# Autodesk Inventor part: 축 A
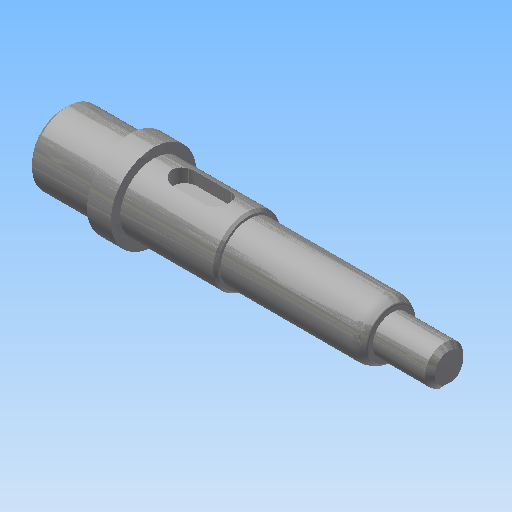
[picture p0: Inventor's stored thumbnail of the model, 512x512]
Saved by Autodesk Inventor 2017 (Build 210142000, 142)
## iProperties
Created: 2020-04
Part Number: 축 A
Material: 강철, 연강
Document SubType Name: Modeling
Designer: mduedu
Density: 7.86 g/cm^3
Mass: 83.1664 g
Surface Area: 37.6212 cm^2
Volume: 10.581 cm^3
Appearance: 강철
Author: mduedu
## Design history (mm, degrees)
sketch "스케치1"
  geometry: L1 (0, 0)-(14, 0); L2 (14, 0)-(14, 7.5); L3 (14, 7.5)-(0, 7.5); L4 (0, 7.5)-(0, 0); L5 (14, 0)-(19, 0); L6 (19, 0)-(19, 9); L7 (19, 9)-(14, 9); L8 (14, 9)-(14, 0); L9 (19, 0)-(39, 0); L10 (39, 0)-(39, 7); L11 (39, 7)-(19, 7); L12 (19, 7)-(19, 0); L13 (39, 0)-(69, 0); L14 (69, 0)-(69, 6); L15 (69, 6)-(39, 6); L16 (39, 6)-(39, 0); L17 (69, 0)-(81, 0); L18 (81, 0)-(81, 4); L19 (81, 4)-(69, 4); L20 (69, 4)-(69, 0)
  constraints: 40 end point, 10 parallel, 5 horizontal, 5 perpendicular
  dimensions: "d0" = 81 distance between parallel lines of L18 L4; "d2" = 14 distance of L2.end L3.end; "d3" = 5 distance of L6.end L7.end; "d4" = 12 distance of L18.end L19.end; "d5" = 8 diameter of L19 L17; "d6" = 12 diameter of L15 L13; "d7" = 14 diameter of L11 L9; "d8" = 15 diameter of L3 L1; "d9" = 18 diameter of L7 L5; "d10" = 42 distance between parallel lines of L10 L18
revolve "회전1" sketch "스케치1" stored, may be unused: angle "d11" = 90 deg
sketch "스케치2"
  geometry: L1 (0, -7.5)-(0, 7.5) reference; L2 (0, 7.5)-(14, 7.5) reference; L3 (14, 7.5)-(14, 9) reference; L4 (14, 9)-(19, 9) reference; L5 (19, 9)-(19, 7) reference; L6 (19, 7)-(39, 7) reference; L7 (39, 7)-(39, 6) reference; L8 (39, 6)-(69, 6) reference; L9 (69, 6)-(69, 4) reference; L10 (69, 4)-(81, 4) reference; L11 (81, 4)-(81, -4) reference; L12 (81, -4)-(69, -4) reference; L13 (69, -4)-(69, -6) reference; L14 (69, -6)-(39, -6) reference; L15 (39, -6)-(39, -7) reference; L16 (39, -7)-(19, -7) reference; L17 (19, -7)-(19, -9) reference; L18 (19, -9)-(14, -9) reference; L19 (14, -9)-(14, -7.5) reference; L20 (14, -7.5)-(0, -7.5) reference; L21 (81, -4)-(73, -4); L22 (73, -4)-(73, -2.8); L23 (73, -2.8)-(81, -2.8); L24 (81, -2.8)-(81, -4); 1 further point
  constraints: 8 end point, 2 parallel, 1 horizontal, 1 perpendicular
  dimensions: "d12" = 8 distance of L22.end L23.end; "d13" = 1.2 distance of L21.end L22.end
extrude "돌출1" cut sketch "스케치2" stored distance "d14" = 2; taper "d15" = 0 deg
fillet "모깎기1" dims "d16" = 1
sketch "스케치3"
  geometry: L1 (0, -7.5)-(0, 7.5) reference; L2 (0, 7.5)-(14, 7.5) reference; L3 (14, 7.5)-(14, 9) reference; L4 (14, 9)-(19, 9) reference; L5 (19, 9)-(19, 7) reference; L6 (19, 7)-(39, 7) reference; L7 (39, 7)-(39, 6) reference; L8 (39, 6)-(69, 6) reference; L9 (69, 6)-(69, 4) reference; L10 (69, 4)-(81, 4) reference; L11 (81, 4)-(81, -2.8) reference; L12 (81, -2.8)-(73, -2.8) reference; L13 (73, -2.8)-(73, -4) reference; L14 (73, -4)-(69, -4) reference; L15 (69, -4)-(69, -6) reference; L16 (69, -6)-(39, -6) reference; L17 (39, -6)-(39, -7) reference; L18 (39, -7)-(19, -7) reference; L19 (19, -7)-(19, -9) reference; L20 (19, -9)-(14, -9) reference; L21 (14, -9)-(14, -7.5) reference; L22 (14, -7.5)-(0, -7.5) reference; L23 (23, 7)-(35, 7); L24 (35, 7)-(35, 4); L25 (35, 4)-(23, 4); L26 (23, 4)-(23, 7); 1 further point
  constraints: 8 end point, 2 parallel, 1 horizontal, 1 perpendicular, 1 point on line
  dimensions: "d17" = 12 distance of L24.end L25.end; "d18" = 3 distance of L23.end L24.end; "d19" = 4 distance from line of L26 L4.end
extrude "돌출2" cut sketch "스케치3" stored distance "d20" = 5; taper "d21" = 0 deg
fillet "모깎기2" dims "d22" = 2.5
chamfer "모따기1" distance "d23" = 1; stored, may be unused: second distance "d24" = 2, angle "d25" = 45 deg
chamfer "모따기2" distance "d26" = 0.5; stored, may be unused: second distance "d27" = 2, angle "d28" = 45 deg
fillet "모깎기3" dims "d29" = 0.3
chamfer "모따기3" distance "d30" = 1.56; stored, may be unused: second distance "d31" = 2, angle "d32" = 30 deg
fillet "모깎기4" dims "d33" = 4, "d34" = 0.5
node "솔리드1"
node "절단 모서리 투영1"
node "절단 모서리 투영2"
